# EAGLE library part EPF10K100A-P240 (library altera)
EPF10K100 FLEX 10K family
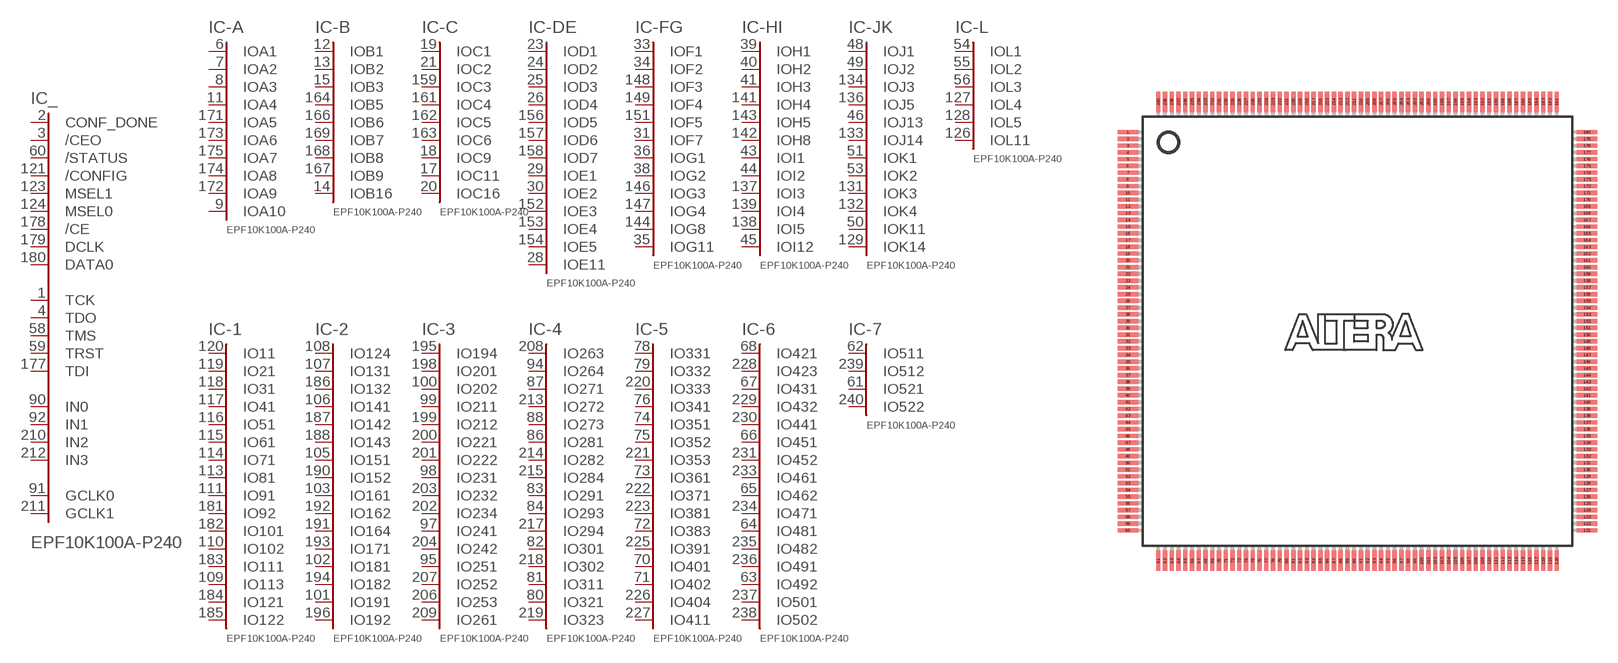
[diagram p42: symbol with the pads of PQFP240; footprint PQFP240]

Designator prefix IC; gates _=100R240C -A=A10-10 -B=B16-100 -C=C16-100 -DE=D7E11 -FG=F7G11 -HI=H8I12 -JK=J14K14 -L=L11-100 -1=122-100R -2=192-100R -3=261-100R -4=323-100R -5=411-100R -6=502-100R -7=522-100R 1=VCCINT 2=VCCINT 3=VCCINT 4=VCCINT 5=VCCINT 6=VCCINT 7=VCCINT 8=VCCINT 9=VCCIO 10=VCCIO 11=VCCIO 12=VCCIO 13=VCCIO 14=VCCIO 15=VCCIO 16=VCCIO 17=VCCIO 18=VCCIO 20=GND 21=GND 22=GND 23=GND 24=GND 25=GND 26=GND 27=GND 28=GND 29=GND 30=GND 31=GND 32=GND 33=GND 34=GND 35=GND 36=GND 37=GND 19=VCC

## EPF10K100A-P240 (MPN: EPF10K100ARC240-1; OC_FARNELL: unknown; OC_NEWARK: 51R8795)  [PQFP240]
1  _:TCK
2  _:CONF_DONE  in
3  _:/CEO  in
4  _:TDO
5  1:VCC  pwr
6  -A:IOA1
7  -A:IOA2
8  -A:IOA3
9  -A:IOA10
10  20:GND  pwr
11  -A:IOA4
12  -B:IOB1
13  -B:IOB2
14  -B:IOB16
15  -B:IOB3
16  10:VCCIO  pwr
17  -C:IOC11
18  -C:IOC9
19  -C:IOC1
20  -C:IOC16
21  -C:IOC2
22  21:GND  pwr
23  -DE:IOD1
24  -DE:IOD2
25  -DE:IOD3
26  -DE:IOD4
27  2:VCC  pwr
28  -DE:IOE11
29  -DE:IOE1
30  -DE:IOE2
31  -FG:IOF7
32  22:GND  pwr
33  -FG:IOF1
34  -FG:IOF2
35  -FG:IOG11
36  -FG:IOG1
37  11:VCCIO  pwr
38  -FG:IOG2
39  -HI:IOH1
40  -HI:IOH2
41  -HI:IOH3
42  23:GND  pwr
43  -HI:IOI1
44  -HI:IOI2
45  -HI:IOI12
46  -JK:IOJ13
47  3:VCC  pwr
48  -JK:IOJ1
49  -JK:IOJ2
50  -JK:IOK11
51  -JK:IOK1
52  24:GND  pwr
53  -JK:IOK2
54  -L:IOL1
55  -L:IOL2
56  -L:IOL3
57  12:VCCIO  pwr
58  _:TMS
59  _:TRST
60  _:/STATUS  in
61  -7:IO521
62  -7:IO511
63  -6:IO492
64  -6:IO481
65  -6:IO462
66  -6:IO451
67  -6:IO431
68  -6:IO421
69  25:GND  pwr
70  -5:IO401
71  -5:IO402
72  -5:IO383
73  -5:IO361
74  -5:IO351
75  -5:IO352
76  -5:IO341
77  13:VCCIO  pwr
78  -5:IO331
79  -5:IO332
80  -4:IO321
81  -4:IO311
82  -4:IO301
83  -4:IO291
84  -4:IO293
85  26:GND  pwr
86  -4:IO281
87  -4:IO271
88  -4:IO273
89  4:VCC  pwr
90  _:IN0  in
91  _:GCLK0  in
92  _:IN1  in
93  27:GND  pwr
94  -4:IO264
95  -3:IO251
96  5:VCC  pwr
97  -3:IO241
98  -3:IO231
99  -3:IO211
100  -3:IO202
101  -2:IO191
102  -2:IO181
103  -2:IO161
104  28:GND  pwr
105  -2:IO151
106  -2:IO141
107  -2:IO131
108  -2:IO124
109  -1:IO113
110  -1:IO102
111  -1:IO91
112  14:VCCIO  pwr
113  -1:IO81
114  -1:IO71
115  -1:IO61
116  -1:IO51
117  -1:IO41
118  -1:IO31
119  -1:IO21
120  -1:IO11
121  _:/CONFIG  in
122  6:VCC  pwr
123  _:MSEL1  in
124  _:MSEL0  in
125  29:GND  pwr
126  -L:IOL11
127  -L:IOL4
128  -L:IOL5
129  -JK:IOK14
130  7:VCC  pwr
131  -JK:IOK3
132  -JK:IOK4
133  -JK:IOJ14
134  -JK:IOJ3
135  30:GND  pwr
136  -JK:IOJ5
137  -HI:IOI3
138  -HI:IOI5
139  -HI:IOI4
140  15:VCCIO  pwr
141  -HI:IOH4
142  -HI:IOH8
143  -HI:IOH5
144  -FG:IOG8
145  31:GND  pwr
146  -FG:IOG3
147  -FG:IOG4
148  -FG:IOF3
149  -FG:IOF4
150  8:VCC  pwr
151  -FG:IOF5
152  -DE:IOE3
153  -DE:IOE4
154  -DE:IOE5
155  32:GND  pwr
156  -DE:IOD5
157  -DE:IOD6
158  -DE:IOD7
159  -C:IOC3
160  16:VCCIO  pwr
161  -C:IOC4
162  -C:IOC5
163  -C:IOC6
164  -B:IOB5
165  33:GND  pwr
166  -B:IOB6
167  -B:IOB9
168  -B:IOB8
169  -B:IOB7
170  9:VCCIO  pwr
171  -A:IOA5
172  -A:IOA9
173  -A:IOA6
174  -A:IOA8
175  -A:IOA7
176  34:GND  pwr
177  _:TDI
178  _:/CE  in
179  _:DCLK  in
180  _:DATA0  in
181  -1:IO92
182  -1:IO101
183  -1:IO111
184  -1:IO121
185  -1:IO122
186  -2:IO132
187  -2:IO142
188  -2:IO143
189  17:VCCIO  pwr
190  -2:IO152
191  -2:IO164
192  -2:IO162
193  -2:IO171
194  -2:IO182
195  -3:IO194
196  -2:IO192
197  35:GND  pwr
198  -3:IO201
199  -3:IO212
200  -3:IO221
201  -3:IO222
202  -3:IO234
203  -3:IO232
204  -3:IO242
205  18:VCCIO  pwr
206  -3:IO253
207  -3:IO252
208  -4:IO263
209  -3:IO261
210  _:IN2  in
211  _:GCLK1  in
212  _:IN3  in
213  -4:IO272
214  -4:IO282
215  -4:IO284
216  36:GND  pwr
217  -4:IO294
218  -4:IO302
219  -4:IO323
220  -5:IO333
221  -5:IO353
222  -5:IO371
223  -5:IO381
224  19:VCC  pwr
225  -5:IO391
226  -5:IO404
227  -5:IO411
228  -6:IO423
229  -6:IO432
230  -6:IO441
231  -6:IO452
232  37:GND  pwr
233  -6:IO461
234  -6:IO471
235  -6:IO482
236  -6:IO491
237  -6:IO501
238  -6:IO502
239  -7:IO512
240  -7:IO522

## Footprint PQFP240 (pad centres in mm)
Plastic Quad Flat Pack
smd 1.5 x 0.32: 1 -17,14.75; 2 -17,14.25; 3 -17,13.75; 4 -17,13.25; 5 -17,12.75; 6 -17,12.25; 7 -17,11.75; 8 -17,11.25; 9 -17,10.75; 10 -17,10.25; 11 -17,9.75; 12 -17,9.25; 13 -17,8.75; 14 -17,8.25; 15 -17,7.75; 16 -17,7.25; 17 -17,6.75; 18 -17,6.25; 19 -17,5.75; 20 -17,5.25; 21 -17,4.75; 22 -17,4.25; 23 -17,3.75; 24 -17,3.25; 25 -17,2.75; 26 -17,2.25; 27 -17,1.75; 28 -17,1.25; 29 -17,0.75; 30 -17,0.25; 31 -17,-0.25; 32 -17,-0.75; 33 -17,-1.25; 34 -17,-1.75; 35 -17,-2.25; 36 -17,-2.75; 37 -17,-3.25; 38 -17,-3.75; 39 -17,-4.25; 40 -17,-4.75; 41 -17,-5.25; 42 -17,-5.75; 43 -17,-6.25; 44 -17,-6.75; 45 -17,-7.25; 46 -17,-7.75; 47 -17,-8.25; 48 -17,-8.75; 49 -17,-9.25; 50 -17,-9.75; 51 -17,-10.25; 52 -17,-10.75; 53 -17,-11.25; 54 -17,-11.75; 55 -17,-12.25; 56 -17,-12.75; 57 -17,-13.25; 58 -17,-13.75; 59 -17,-14.25; 60 -17,-14.75; 121 17,-14.75; 122 17,-14.25; 123 17,-13.75; 124 17,-13.25; 125 17,-12.75; 126 17,-12.25; 127 17,-11.75; 128 17,-11.25; 129 17,-10.75; 130 17,-10.25; 131 17,-9.75; 132 17,-9.25; 133 17,-8.75; 134 17,-8.25; 135 17,-7.75; 136 17,-7.25; 137 17,-6.75; 138 17,-6.25; 139 17,-5.75; 140 17,-5.25; 141 17,-4.75; 142 17,-4.25; 143 17,-3.75; 144 17,-3.25; 145 17,-2.75; 146 17,-2.25; 147 17,-1.75; 148 17,-1.25; 149 17,-0.75; 150 17,-0.25; 151 17,0.25; 152 17,0.75; 153 17,1.25; 154 17,1.75; 155 17,2.25; 156 17,2.75; 157 17,3.25; 158 17,3.75; 159 17,4.25; 160 17,4.75; 161 17,5.25; 162 17,5.75; 163 17,6.25; 164 17,6.75; 165 17,7.25; 166 17,7.75; 167 17,8.25; 168 17,8.75; 169 17,9.25; 170 17,9.75; 171 17,10.25; 172 17,10.75; 173 17,11.25; 174 17,11.75; 175 17,12.25; 176 17,12.75; 177 17,13.25; 178 17,13.75; 179 17,14.25; 180 17,14.75
smd 0.32 x 1.5: 61 -14.75,-17; 62 -14.25,-17; 63 -13.75,-17; 64 -13.25,-17; 65 -12.75,-17; 66 -12.25,-17; 67 -11.75,-17; 68 -11.25,-17; 69 -10.75,-17; 70 -10.25,-17; 71 -9.75,-17; 72 -9.25,-17; 73 -8.75,-17; 74 -8.25,-17; 75 -7.75,-17; 76 -7.25,-17; 77 -6.75,-17; 78 -6.25,-17; 79 -5.75,-17; 80 -5.25,-17; 81 -4.75,-17; 82 -4.25,-17; 83 -3.75,-17; 84 -3.25,-17; 85 -2.75,-17; 86 -2.25,-17; 87 -1.75,-17; 88 -1.25,-17; 89 -0.75,-17; 90 -0.25,-17; 91 0.25,-17; 92 0.75,-17; 93 1.25,-17; 94 1.75,-17; 95 2.25,-17; 96 2.75,-17; 97 3.25,-17; 98 3.75,-17; 99 4.25,-17; 100 4.75,-17; 101 5.25,-17; 102 5.75,-17; 103 6.25,-17; 104 6.75,-17; 105 7.25,-17; 106 7.75,-17; 107 8.25,-17; 108 8.75,-17; 109 9.25,-17; 110 9.75,-17; 111 10.25,-17; 112 10.75,-17; 113 11.25,-17; 114 11.75,-17; 115 12.25,-17; 116 12.75,-17; 117 13.25,-17; 118 13.75,-17; 119 14.25,-17; 120 14.75,-17; 181 14.75,17; 182 14.25,17; 183 13.75,17; 184 13.25,17; 185 12.75,17; 186 12.25,17; 187 11.75,17; 188 11.25,17; 189 10.75,17; 190 10.25,17; 191 9.75,17; 192 9.25,17; 193 8.75,17; 194 8.25,17; 195 7.75,17; 196 7.25,17; 197 6.75,17; 198 6.25,17; 199 5.75,17; 200 5.25,17; 201 4.75,17; 202 4.25,17; 203 3.75,17; 204 3.25,17; 205 2.75,17; 206 2.25,17; 207 1.75,17; 208 1.25,17; 209 0.75,17; 210 0.25,17; 211 -0.25,17; 212 -0.75,17; 213 -1.25,17; 214 -1.75,17; 215 -2.25,17; 216 -2.75,17; 217 -3.25,17; 218 -3.75,17; 219 -4.25,17; 220 -4.75,17; 221 -5.25,17; 222 -5.75,17; 223 -6.25,17; 224 -6.75,17; 225 -7.25,17; 226 -7.75,17; 227 -8.25,17; 228 -8.75,17; 229 -9.25,17; 230 -9.75,17; 231 -10.25,17; 232 -10.75,17; 233 -11.25,17; 234 -11.75,17; 235 -12.25,17; 236 -12.75,17; 237 -13.25,17; 238 -13.75,17; 239 -14.25,17; 240 -14.75,17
